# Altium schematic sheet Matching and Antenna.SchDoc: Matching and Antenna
size A4; PageSetup: Record=PageOptions¦CenterHorizontal=True¦CenterVertical=True¦PrintScale=0.97¦XCorrection=1.00¦YCorrection=1.00¦PrintKind=0¦BorderSize=5000000¦LeftOffset=0¦BottomOffset=0¦Orientation=2¦PaperLength=1000¦PaperWidth=1000¦Scale=100¦PaperSource=7¦PrintQuality=-4¦MediaType=1¦DitherType=10¦PaperKind=A4¦PrintScaleMode=1; Date: Not used; ApprovedBy: Not used; CheckedBy: Not used; Author: Not used; CompanyName: STMicroelectronics; DrawnBy: Not used; Engineer: Not used; Organization: Not used; Address1: Not used; Address2: Not used; Address3: Not used; Address4: Not used; DocumentNumber: 4; Revision: Not used; SheetNumber: 5; SheetTotal: 5
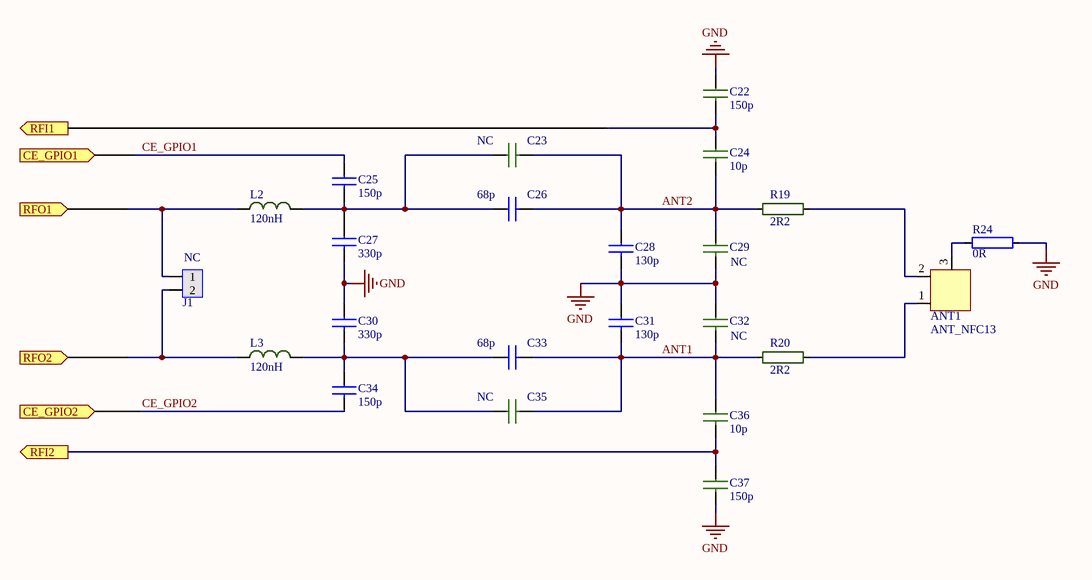
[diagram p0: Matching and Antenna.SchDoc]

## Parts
ANT1  ANT_NFC13  [ANT_NFC08]  (net tie, no BOM)
C22  150p  [C0402]
C23  100p  [C0603]  (value not drawn)
C24  10p  [C0402]
C25  150p  [C0603]
C26  68p  [C0603]
C27  330p  [C0603]
C28  130p  [C0603]
C29  6p8  [C0603]  (value not drawn)
C30  330p  [C0603]
C31  130p  [C0603]
C32  6p8  [C0603]  (value not drawn)
C33  68p  [C0603]
C34  150p  [C0603]
C35  100p  [C0603]  (value not drawn)
C36  10p  [C0402]
C37  150p  [C0402]
J1  NC  [HDR1X2_slim]  (no BOM)
L2  120nH  [L0603]
L3  120nH  [L0603]
R19  2R2  [R0603]
R20  2R2  [R0603]
R24  0R  [R0402]

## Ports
CE_GPIO1 (in), CE_GPIO2 (in), RFI1 (out), RFI2 (out), RFO1 (in), RFO2 (in)

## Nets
GND: C22.1 C27.2 C28.2 C29.2 C30.1 C31.1 C32.1 C37.2 R24.1
ANT1: C31.2 C32.2 C33.2 C35.2 C36.1 R20.2
ANT2: C23.2 C24.2 C26.2 C28.1 C29.1 R19.2
CE_GPIO1: C25.1 ; port CE_GPIO1
CE_GPIO2: C34.2 ; port CE_GPIO2
RFI1: C22.2 C24.1 ; port RFI1
RFI2: C36.2 C37.1 ; port RFI2
RFO1: J1.1 L2.2 ; port RFO1
RFO2: J1.2 L3.2 ; port RFO2
NetANT1_1: ANT1.1 R20.1
NetANT1_2: ANT1.2 R19.1
NetANT1_3: ANT1.3 R24.2
NetC23_1: C23.1 C25.2 C26.1 C27.1 L2.1
NetC30_2: C30.2 C33.1 C34.1 C35.1 L3.1

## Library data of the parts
ANT1 = ANT_NFC06
C22 C37 = C_150p_0402_AEC-Q: 150p_COG; Manufacturer: Murata; Manufacturer Part Number: GCM1555C1H151FA16D; 2nd Source: AEC-Q200 150pF ±1% 50V  C0G 0402
C23 C35 = C_100p_0603_AEC-Q: 100p_COG; Manufacturer: Murta; Manufacturer Part Number: GCM1885C2A101FA16D; 2nd Source: AEC-Q200 100pF ±1% 100V  C0G 0603
C24 C36 = C_10p_0402_AEC-Q: 10p_COG; Manufacturer: Murata; Manufacturer Part Number: GCM1555C1H100FA16D; 2nd Source: AEC-Q200 10pF ±1% 100V  C0G 0402
C25 C34 = C_150p_0603: 150p_COG; Manufacturer: KEMET; Manufacturer Part Number: C0603C151F5GACTU; 2nd Source: 150pF ±1% 50V  C0G, NP0 0603
C26 C33 = C_68p_0603: 68p_COG; Manufacturer: KEMET; Manufacturer Part Number: C0603C680F1GACTU; 2nd Source: 68pF ±1% 100V  C0G, NP0 0603
C27 C30 = C_330p_0603: 330p_COG; Manufacturer: YAGEO; Manufacturer Part Number: CC0603FRNPO9BN331; 2nd Source: 330pF ±1% 50V  C0G, NP0 0603
C28 C31 = C_130p_0603: 130p_COG; Manufacturer: KEMET; Manufacturer Part Number: C0603C131F5GACTU; 2nd Source: 130pF ±1% 50V  C0G, NP0 0603
C29 C32 = C_6.8p_0603: 6.8p_COG; Manufacturer: KEMET; Manufacturer Part Number: C0603C689J5GACTU; 2nd Source: 6.8pF 50V  C0G 0603
J1 = Header 2: Male Single Row Horizontal 2 pin; 2nd Source: doublesourcing allowed
L2 L3 = L0603_120nH: LQW18CNR27J0ZD; Manufacturer: Murata; Manufacturer Part Number: LQW18CNR12J0ZD; 2nd Source: no
R19 R20 = R0603_2R2: 2R2, 0603; Manufacturer: Vishay Dale; Manufacturer Part Number: CRCW06032R20FKEA; 2nd Source: 2.2 Ohm ±1% 0.1W, 1/10W Chip Resistor 0603
R24 = R0402_0R: 0R, 0402; Manufacturer: VISHAY; Manufacturer Part Number: CRCW04020000ZSTD; 2nd Source: 0 ohm, 50 V, 0402, >62.5 mW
